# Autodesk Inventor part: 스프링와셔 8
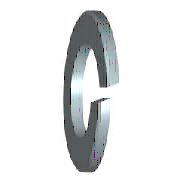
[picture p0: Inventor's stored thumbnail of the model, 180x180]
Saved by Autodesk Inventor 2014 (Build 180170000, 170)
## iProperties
IsCustomPart: 1
Created: 2012-02
Part Number: 스프링와셔 8
Material: 강철, 연강
Description: 스프링 잠금 와셔
Document SubType Name: Modeling
Standard: KS B 1324
Designer: mduedu
Standards Organization: KS
Language: ko-KR
Size Designation: 번호 3 - 8
Categories: <MemberInstance><Categories><Category DisplayName="조임쇠" InternalName="e4da775c-781d-43d5-af7c-5136215cf5a6" Mnemonic="FSTN"><Category DisplayName="와셔" InternalN
Density: 1 g/cm^3
Appearance: 파란색 - 벽 페인트 - 광택
Author: mduedu
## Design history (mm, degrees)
sketch "스케치1"
  geometry: C1 r 7.4 at (0, 0); C2 r 4.1 at (0, 0); 1 further point
  constraints: 2 centre point, 2 coincident
  dimensions: "d0" = 8.2 diameter of C2 (= SD1); "d1" = 14.8 diameter of C1 (= SD2)
extrude "본체" new body sketch "스케치1" distance "d2" = 2.5 (= SD); taper "d3" = 0 deg
sketch "스케치2"
  geometry: L1 (0, -4.1)-(0, 4.1) reference; L2 (2.5, 7.4)-(2.5, -7.4) reference; L3 (-1.2, 0)-(7.2, 0) reference; L4 (0, -0.5)-(2.5, 0.41); L5 (0, 0.5)-(2.5, 1.41)
  constraints: 4 end point, 4 point on line, 1 parallel
  dimensions: "d4" = 0.5 distance from line of L3 L4.start (= 0.2 x SD); "d5" = 0.5 distance from line of L3 L5.start (= 0.2 x SD); "d6" = 70 deg angle of L2 L4 (= FAWI)
extrude "절단부" cut sketch "스케치2" stored distance "d7" = 2.5 (= SD); taper "d8" = 0 deg
workaxis "Work Axis1"
workplane "Work Plane1"
body "Solid1"
other parameters: "SD1" = 8.2 [user parameter; used in 1 equation term], "SD2" = 14.8 [user parameter; used in 1 equation term], "SD" = 2.5 [user parameter; used in 4 equation terms], "FAWI" = 70 deg [user parameter; used in 1 equation term], "d9" = 0, "d10" = 0, "d11" = 0, "d12" = 0, "SDI" = 3.3 [user parameter], "NND" = 8 [user parameter]
